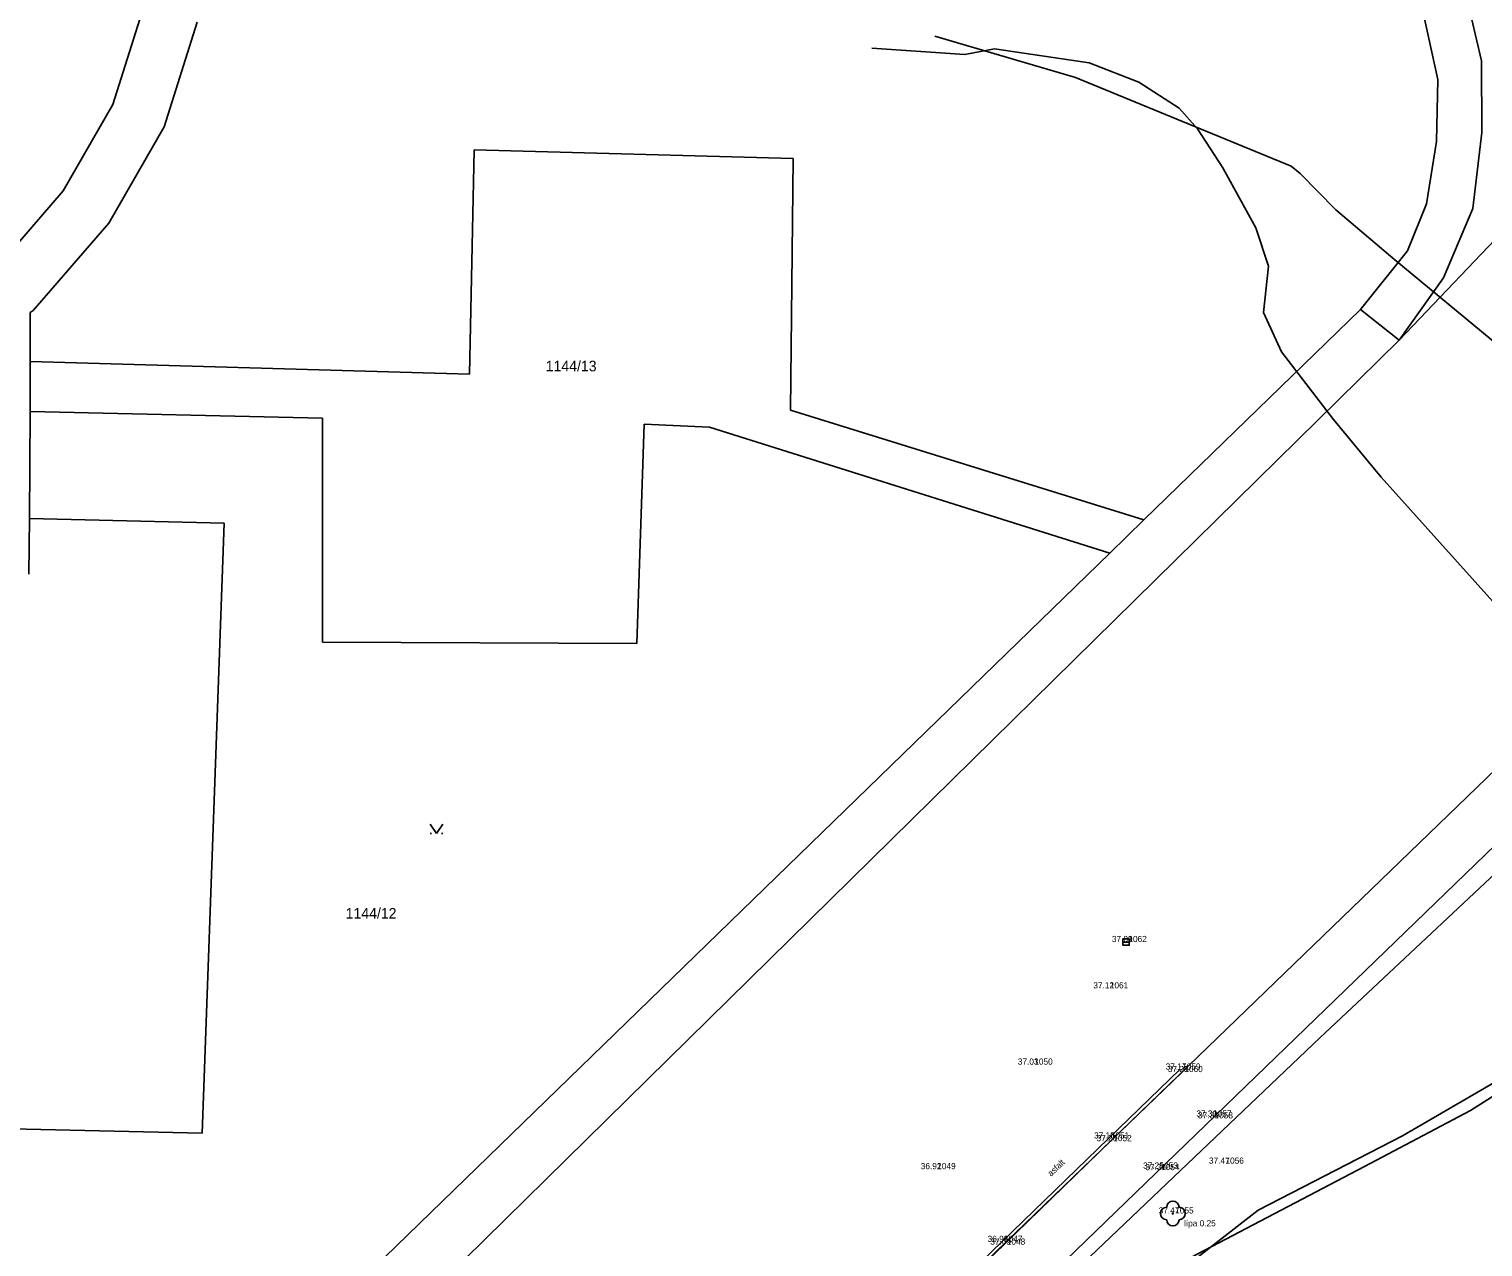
# Model space of a CAD drawing. Extents: x -609709 to -609357, y -1051535 to -1051131.
# Drawn here: x -609617.6 to -609558.8, y -1051228.1 to -1051178.9 of the extents above; entities that cross this region are included whole.
import ezdxf

# ---------------------------------------------------------------- set-up
doc = ezdxf.new("R2010")
doc.units = 0
for name, color, linetype in [('Vrstva 1', 7, 'Continuous'), ('Vrstva 10', 7, 'Continuous'), ('Vrstva 15', 7, 'Continuous'), ('Vrstva 17', 7, 'Continuous'), ('Vrstva 2', 7, 'Continuous'), ('Vrstva 3', 7, 'Continuous'), ('Vrstva 4', 7, 'Continuous'), ('Vrstva 5', 7, 'Continuous'), ('Vrstva 7', 7, 'Continuous')]:
    doc.layers.add(name, color=color, linetype=linetype)

msp = doc.modelspace()

# ---------------------------------------------------------------- linework, layer by layer
at = {"layer": 'Vrstva 1'}
for p, q in [((-609573.25, -1051215.77), (-609573.25, -1051215.77)), ((-609574, -1051217.64), (-609574, -1051217.64)), ((-609577.05, -1051220.72), (-609577.05, -1051220.72)), ((-609571.08, -1051220.92), (-609571.08, -1051220.92)), ((-609570.99, -1051221.02), (-609570.99, -1051221.02)), ((-609569.83, -1051222.82), (-609569.83, -1051222.82)), ((-609569.77, -1051222.89), (-609569.77, -1051222.89)), ((-609573.96, -1051223.7), (-609573.96, -1051223.7)), ((-609573.86, -1051223.81), (-609573.86, -1051223.81)), ((-609569.33, -1051224.72), (-609569.33, -1051224.72)), ((-609580.97, -1051224.94), (-609580.97, -1051224.94)), ((-609571.99, -1051224.92), (-609571.99, -1051224.92)), ((-609571.93, -1051224.98), (-609571.93, -1051224.98)), ((-609571.36, -1051226.73), (-609571.36, -1051226.73)), ((-609578.27, -1051227.88), (-609578.27, -1051227.88)), ((-609578.16, -1051227.99), (-609578.16, -1051227.99))]:
    msp.add_line(p, q, dxfattribs=at)
at = {"layer": 'Vrstva 10'}
for p, q in [((-609562.22, -1051191.46), (-609540.81, -1051169.01)), ((-609561.36, -1051177.74), (-609560.66, -1051180.94)), ((-609559.59, -1051177.24), (-609558.89, -1051180.18)), ((-609614.17, -1051181.94), (-609613, -1051178.24)), ((-609612.1, -1051182.85), (-609610.76, -1051178.62)), ((-609558.89, -1051180.18), (-609558.88, -1051183.07)), ((-609560.72, -1051183.44), (-609560.66, -1051180.94)), ((-609616.18, -1051185.43), (-609614.17, -1051181.94)), ((-609614.34, -1051186.74), (-609612.1, -1051182.85)), ((-609561.12, -1051185.96), (-609560.72, -1051183.44)), ((-609559.24, -1051186.14), (-609558.88, -1051183.07)), ((-609599.77, -1051192.83), (-609599.58, -1051183.77)), ((-609599.58, -1051183.77), (-609586.69, -1051184.12)), ((-609586.81, -1051194.29), (-609586.69, -1051184.12)), ((-609618.86, -1051188.53), (-609616.18, -1051185.43)), ((-609561.89, -1051187.86), (-609561.12, -1051185.96)), ((-609560.43, -1051188.94), (-609559.24, -1051186.14)), ((-609617.39, -1051190.27), (-609614.34, -1051186.74)), ((-609563.78, -1051190.22), (-609561.89, -1051187.86)), ((-609562.22, -1051191.46), (-609560.43, -1051188.94)), ((-609617.51, -1051190.34), (-609617.39, -1051190.27)), ((-609617.51, -1051190.34), (-609617.51, -1051192.33)), ((-609572.53, -1051198.72), (-609563.78, -1051190.22)), ((-609563.78, -1051190.22), (-609562.22, -1051191.46)), ((-609612.01, -1051240.42), (-609562.22, -1051191.46)), ((-609617.51, -1051194.34), (-609617.51, -1051192.33)), ((-609617.51, -1051192.33), (-609599.77, -1051192.83)), ((-609617.54, -1051198.66), (-609617.51, -1051194.34)), ((-609617.51, -1051194.34), (-609605.7, -1051194.61)), ((-609605.7, -1051194.61), (-609605.7, -1051203.66)), ((-609586.81, -1051194.29), (-609572.53, -1051198.72)), ((-609593.01, -1051203.71), (-609592.71, -1051194.86)), ((-609592.71, -1051194.86), (-609590.08, -1051194.98)), ((-609590.08, -1051194.98), (-609573.91, -1051200.06)), ((-609617.57, -1051200.91), (-609617.54, -1051198.66)), ((-609617.54, -1051198.66), (-609609.68, -1051198.85)), ((-609610.56, -1051223.48), (-609609.68, -1051198.85)), ((-609573.91, -1051200.06), (-609572.53, -1051198.72)), ((-609611.96, -1051237), (-609573.91, -1051200.06)), ((-609605.7, -1051203.66), (-609593.01, -1051203.71)), ((-609582.07, -1051231.71), (-609553.74, -1051204.36)), ((-609581.13, -1051233.87), (-609552.07, -1051205.79)), ((-609601.35, -1051211.005), (-609601.1, -1051211.38)), ((-609601.1, -1051211.38), (-609600.85, -1051211.005)), ((-609601.35, -1051211.38), (-609601.3, -1051211.38)), ((-609600.9, -1051211.38), (-609600.85, -1051211.38)), ((-609621.19, -1051223.24), (-609610.56, -1051223.48))]:
    msp.add_line(p, q, dxfattribs=at)
at = {"layer": 'Vrstva 15'}
for points in [[(-609580.98, -1051179.18), (-609575.29, -1051180.86), (-609566.58, -1051184.44), (-609566.22, -1051184.73), (-609564.78, -1051186.2), (-609562.39, -1051188.22), (-609546.83, -1051201.09), (-609540.61, -1051205.12), (-609539.62, -1051205.91), (-609537.51, -1051208.58), (-609535.67, -1051207.94), (-609527.2, -1051200.98), (-609524.08, -1051200.22), (-609521.08, -1051202.07)], [(-609557.49, -1051203.06), (-609562.95, -1051197), (-609564.87, -1051194.66), (-609566.98, -1051191.94), (-609567.7, -1051190.34), (-609567.5, -1051188.48), (-609568.01, -1051186.92), (-609569.34, -1051184.5), (-609570.37, -1051182.93), (-609571.1, -1051182.09), (-609572.73, -1051181.05), (-609574.74, -1051180.26), (-609578.56, -1051179.7), (-609579.76, -1051179.93), (-609583.52, -1051179.67)], [(-609537.51, -1051208.58), (-609541.98, -1051211.54), (-609559.34, -1051222.57), (-609563.62, -1051224.83), (-609573.15, -1051229.82), (-609581.51, -1051234.92), (-609583.83, -1051237.49), (-609593.84, -1051247.18), (-609592.54, -1051249), (-609587.23, -1051247.57), (-609586.1, -1051248.66), (-609581.84, -1051254.04), (-609580.215, -1051257.976)], [(-609575.07, -1051232.15), (-609567.92, -1051226.6), (-609562.09, -1051223.59), (-609556.37, -1051220.27)]]:
    msp.add_lwpolyline(points, dxfattribs=at)
at = {"layer": 'Vrstva 17'}
msp.add_lwpolyline([(-609531.786, -1051180.515), (-609532.61, -1051181.07), (-609528.54, -1051185.58), (-609545.95, -1051201.69), (-609546.72, -1051202.27), (-609551.04, -1051206.15), (-609565.42, -1051219.63), (-609579.77, -1051233.3), (-609583.56, -1051235.84), (-609591.75, -1051241.92), (-609609.05, -1051258.52), (-609618.01, -1051267.11), (-609626.05, -1051275.26), (-609630.23, -1051279.58), (-609635.78, -1051285.7), (-609642.85, -1051291.4), (-609672.95, -1051307.23)], dxfattribs=at)
at = {"layer": 'Vrstva 4'}
for points in [[(-609581.15, -1051230.66), (-609578.27, -1051227.88), (-609573.96, -1051223.7), (-609571.08, -1051220.92)], [(-609581.054, -1051230.761), (-609578.173, -1051227.981), (-609573.863, -1051223.801), (-609570.983, -1051221.021)]]:
    msp.add_lwpolyline(points, dxfattribs=at)
at = {"layer": 'Vrstva 5'}
msp.add_line((-609573.375, -1051215.77), (-609573.125, -1051215.77), dxfattribs=at)
msp.add_lwpolyline([(-609573.375, -1051215.645), (-609573.125, -1051215.645), (-609573.125, -1051215.895), (-609573.375, -1051215.895)], close=True, dxfattribs=at)
at = {"layer": 'Vrstva 7'}
msp.add_circle((-609571.36, -1051226.73), 0.025, dxfattribs=at)
for centre, start, end in [((-609571.61, -1051226.73), 90, 270), ((-609571.36, -1051226.48), 0, 180), ((-609571.11, -1051226.73), 270, 90), ((-609571.36, -1051226.98), 180, 0)]:
    msp.add_arc(centre, 0.25, start, end, dxfattribs=at)

# ---------------------------------------------------------------- texts
at = {"layer": 'Vrstva 10'}
for s, p in [('1144/13', (-609596.69, -1051192.72)), ('1144/12', (-609604.77, -1051214.82))]:
    msp.add_text(s, height=0.425, dxfattribs=at).set_placement(p)
at = {"layer": 'Vrstva 2'}
for s, p in [(' 1062', (-609573.25, -1051215.77)), (' 1061', (-609574, -1051217.64)), (' 1050', (-609577.05, -1051220.72)), (' 1059', (-609571.08, -1051220.92)), (' 1060', (-609570.99, -1051221.02)), (' 1057', (-609569.83, -1051222.82)), (' 1058', (-609569.77, -1051222.89)), (' 1051', (-609573.96, -1051223.7)), (' 1052', (-609573.86, -1051223.81)), (' 1049', (-609580.97, -1051224.94)), (' 1053', (-609571.99, -1051224.92)), (' 1054', (-609571.93, -1051224.98)), (' 1056', (-609569.33, -1051224.72)), (' 1055', (-609571.36, -1051226.73)), (' 1047', (-609578.27, -1051227.88)), (' 1048', (-609578.16, -1051227.99))]:
    msp.add_text(s, height=0.25, dxfattribs=at).set_placement(p)
at = {"layer": 'Vrstva 3'}
for s, p in [('37.09', (-609573.823, -1051215.77)), ('37.12', (-609574.573, -1051217.64)), ('37.03', (-609577.623, -1051220.72)), ('37.17', (-609571.653, -1051220.92)), ('37.28', (-609571.563, -1051221.02)), ('37.30', (-609570.413, -1051222.82)), ('37.36', (-609570.349, -1051222.89)), ('37.10', (-609574.543, -1051223.7)), ('37.20', (-609574.443, -1051223.81)), ('36.92', (-609581.543, -1051224.94)), ('37.25', (-609572.563, -1051224.92)), ('37.31', (-609572.472, -1051224.98)), ('37.47', (-609569.903, -1051224.72)), ('37.47', (-609571.933, -1051226.73)), ('36.98', (-609578.843, -1051227.88)), ('37.09', (-609578.733, -1051227.99))]:
    msp.add_text(s, height=0.25, dxfattribs=at).set_placement(p)
at = {"layer": 'Vrstva 4'}
msp.add_text('asfalt', height=0.25, rotation=44.12275, dxfattribs=at).set_placement((-609576.278, -1051225.251))
at = {"layer": 'Vrstva 7'}
msp.add_text('lípa 0.25', height=0.25, dxfattribs=at).set_placement((-609570.91, -1051227.25))

doc.saveas('drawing.dxf')
